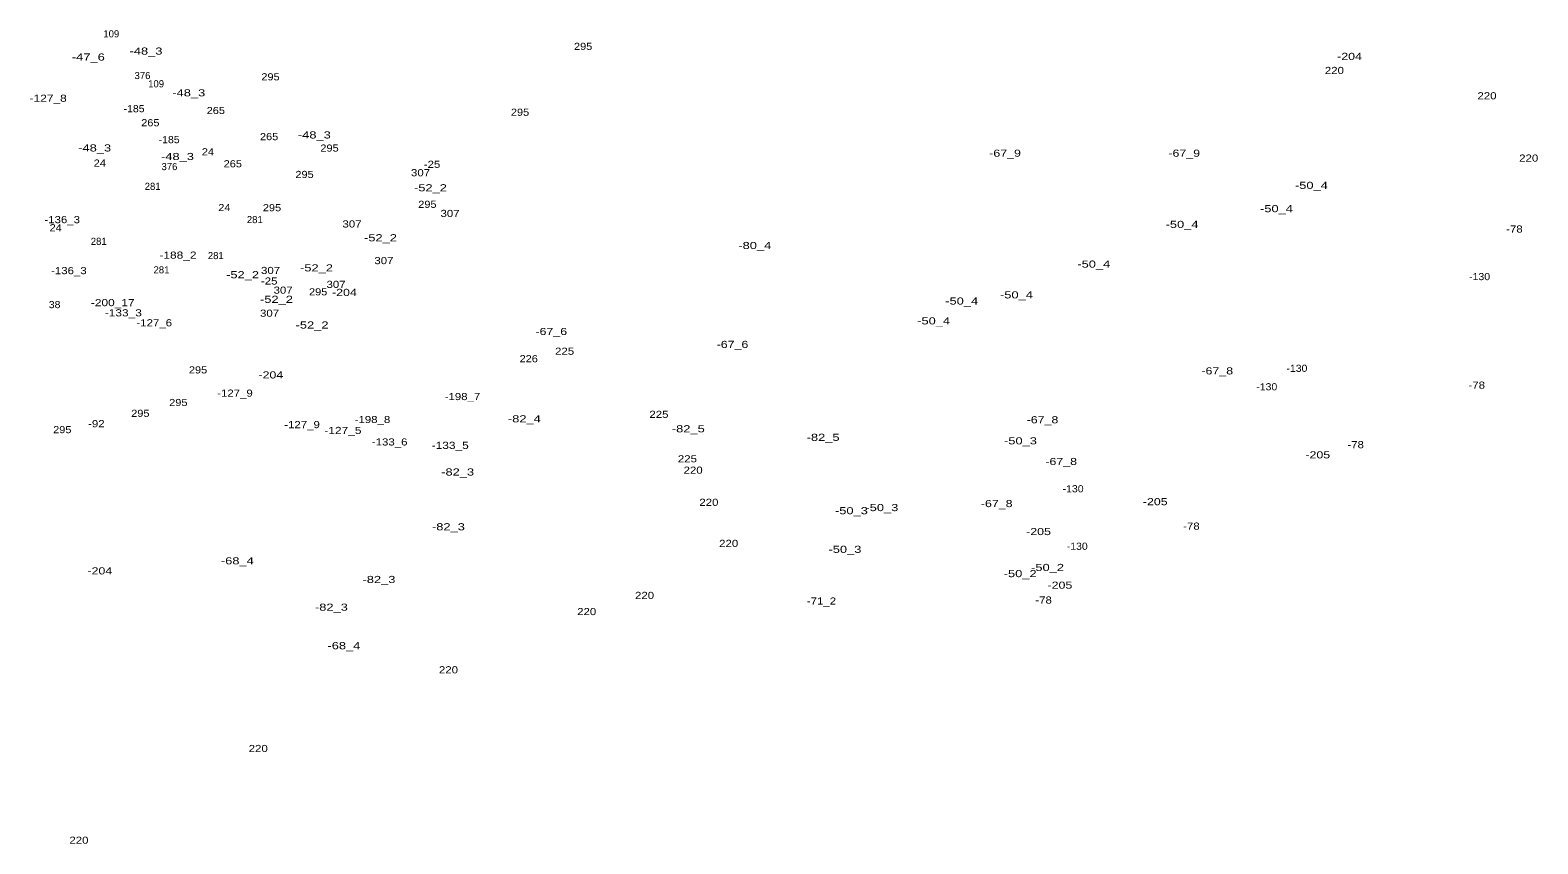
# Model space of a CAD drawing. Extents: x -662996 to -659766, y -998554 to -993949.
# Drawn here: x -660995 to -660149, y -995562 to -995106 of the extents above; entities that cross this region are included whole.
import ezdxf
from ezdxf.enums import TextEntityAlignment as Align

# ---------------------------------------------------------------- set-up
doc = ezdxf.new("R2010")
doc.units = 0
doc.header["$LTSCALE"] = 1.6
doc.layers.add('24', color=7, linetype='Continuous')

msp = doc.modelspace()

# ---------------------------------------------------------------- texts
at = {"layer": '24'}
for s, p in [('109', (-660949.441, -995109.63)), ('376', (-660931.938, -995133.05)), ('109', (-660924.291, -995137.67)), ('376', (-660916.798, -995184.14)), ('281', (-660926.22, -995195.24)), ('281', (-660868.9, -995213.9)), ('281', (-660956.49, -995226.1)), ('281', (-660921.27, -995242.1)), ('281', (-660890.799, -995234.1))]:
    msp.add_text(s, height=4, dxfattribs=at).set_placement(p, align=Align.CENTER)
for s, width, p in [('-47_6', 1.35, (-660962.311, -995122.64)), ('-48_3', 1.35, (-660929.95, -995119.32)), ('295', 1.15, (-660684.65, -995116.68)), ('-204', 1.3, (-660254.58, -995122.3)), ('220', 1.2, (-660263.079, -995130.19)), ('295', 1.15, (-660860.09, -995133.75)), ('-127_8', 1.25, (-660984.85, -995145.79)), ('-48_3', 1.35, (-660905.95, -995142.75)), ('220', 1.2, (-660177.449, -995144.41)), ('-185', 1.1, (-660936.65, -995151.64)), ('265', 1.15, (-660890.77, -995152.67)), ('295', 1.15, (-660720.07, -995153.63)), ('265', 1.15, (-660927.52, -995159.52)), ('-48_3', 1.35, (-660958.76, -995173.68)), ('-185', 1.1, (-660916.971, -995169.01)), ('265', 1.15, (-660860.87, -995167.33)), ('-48_3', 1.35, (-660835.49, -995166.38)), ('295', 1.15, (-660826.96, -995173.75)), ('24', 1.15, (-660955.87, -995182.17)), ('-48_3', 1.35, (-660912.29, -995178.48)), ('24', 1.15, (-660895.199, -995175.83)), ('265', 1.15, (-660881.25, -995182.57)), ('-25', 1.2, (-660769.44, -995182.88)), ('-67_9', 1.3, (-660447.89, -995176.63)), ('-67_9', 1.3, (-660347.35, -995176.63)), ('220', 1.2, (-660154.02, -995179.37)), ('295', 1.15, (-660840.98, -995188.55)), ('307', 1.2, (-660775.9, -995187.59)), ('-52_2', 1.35, (-660770.34, -995196.04)), ('-50_4', 1.35, (-660275.99, -995194.69)), ('24', 1.15, (-660885.98, -995207.14)), ('295', 1.15, (-660859.25, -995207.21)), ('295', 1.15, (-660772.05, -995205.31)), ('-50_4', 1.35, (-660295.58, -995207.75)), ('-136_3', 1.2, (-660976.981, -995213.92)), ('307', 1.2, (-660814.36, -995216.35)), ('307', 1.2, (-660759.33, -995210.44)), ('-50_4', 1.35, (-660348.57, -995216.59)), ('24', 1.15, (-660980.64, -995218.47)), ('-52_2', 1.35, (-660798.38, -995224.09)), ('-78', 1.2, (-660162.071, -995219.21)), ('-188_2', 1.25, (-660912.01, -995233.84)), ('-80_4', 1.35, (-660588.34, -995228.44)), ('-52_2', 1.35, (-660834.28, -995240.99)), ('307', 1.2, (-660796.46, -995236.92)), ('-50_4', 1.35, (-660398.11, -995238.87)), ('-136_3', 1.2, (-660973.24, -995242.54)), ('-52_2', 1.35, (-660875.76, -995244.83)), ('-25', 1.2, (-660860.83, -995248.38)), ('307', 1.2, (-660860.06, -995242.44)), ('307', 1.2, (-660823.31, -995250.25)), ('-130', 1.1, (-660181.601, -995245.89)), ('-52_2', 1.35, (-660856.75, -995258.66)), ('307', 1.2, (-660853.01, -995253.49)), ('295', 1.15, (-660833.36, -995254.45)), ('-204', 1.3, (-660818.61, -995254.76)), ('-50_4', 1.35, (-660441.5, -995256.15)), ('38', 1.1, (-660981.25, -995261.61)), ('-200_17', 1.25, (-660948.62, -995260.51)), ('-133_3', 1.25, (-660942.689, -995266.22)), ('307', 1.2, (-660860.63, -995266.44)), ('-50_4', 1.35, (-660472.22, -995259.61)), ('-127_6', 1.2, (-660925.32, -995271.81)), ('-52_2', 1.35, (-660836.78, -995273.07)), ('-50_4', 1.35, (-660487.97, -995270.75)), ('-67_6', 1.3, (-660702.53, -995276.71)), ('-67_6', 1.3, (-660600.85, -995283.95)), ('226', 1.15, (-660715.19, -995291.97)), ('225', 1.2, (-660695.059, -995287.78)), ('295', 1.15, (-660900.76, -995298.26)), ('-204', 1.3, (-660859.9, -995301.08)), ('-67_8', 1.3, (-660328.821, -995298.81)), ('-130', 1.1, (-660284.13, -995297.36)), ('-130', 1.1, (-660301.03, -995307.73)), ('-78', 1.2, (-660183.191, -995306.8)), ('295', 1.15, (-660911.81, -995316.55)), ('-127_9', 1.2, (-660880.03, -995311.3)), ('-198_7', 1.2, (-660752.36, -995313.22)), ('295', 1.15, (-660933.13, -995322.64)), ('-198_8', 1.2, (-660802.87, -995326.11)), ('-82_4', 1.35, (-660717.63, -995325.71)), ('225', 1.2, (-660642.13, -995323.21)), ('-67_8', 1.3, (-660426.88, -995326.24)), ('295', 1.15, (-660976.93, -995331.79)), ('-92', 1.2, (-660957.82, -995328.45)), ('-127_9', 1.2, (-660842.39, -995328.98)), ('-127_5', 1.25, (-660819.45, -995332.24)), ('-82_5', 1.35, (-660625.64, -995331.31)), ('-133_6', 1.2, (-660793.231, -995338.69)), ('-133_5', 1.25, (-660759.24, -995340.61)), ('-82_5', 1.35, (-660549.99, -995336.11)), ('-50_3', 1.35, (-660439.25, -995338.09)), ('-78', 1.2, (-660251.16, -995340.22)), ('225', 1.2, (-660626.13, -995348.17)), ('-67_8', 1.3, (-660416.4, -995349.67)), ('-205', 1.3, (-660272.41, -995345.95)), ('-82_3', 1.35, (-660755.069, -995355.57)), ('220', 1.2, (-660622.939, -995354.54)), ('-130', 1.1, (-660409.701, -995364.97)), ('220', 1.2, (-660614.1, -995372.59)), ('-50_3', 1.35, (-660534.11, -995377.27)), ('-50_3', 1.35, (-660517.02, -995375.54)), ('-67_8', 1.3, (-660452.581, -995373.29)), ('-205', 1.3, (-660363.61, -995372.23)), ('-78', 1.2, (-660343.321, -995385.94)), ('-82_3', 1.35, (-660760.25, -995386.31)), ('-205', 1.3, (-660429.11, -995388.99)), ('220', 1.2, (-660602.97, -995395.64)), ('-50_3', 1.35, (-660537.75, -995398.97)), ('-130', 1.1, (-660407.4, -995397.24)), ('-204', 1.3, (-660955.86, -995411.06)), ('-68_4', 1.35, (-660878.7, -995405.43)), ('-50_2', 1.35, (-660424.049, -995409.14)), ('-82_3', 1.35, (-660799.23, -995415.89)), ('-50_2', 1.35, (-660439.41, -995412.6)), ('-205', 1.3, (-660417.12, -995419.09)), ('220', 1.2, (-660650.199, -995424.84)), ('-71_2', 1.2, (-660550.94, -995428)), ('-78', 1.2, (-660426.27, -995427.43)), ('-82_3', 1.35, (-660825.919, -995431.44)), ('220', 1.2, (-660682.65, -995433.92)), ('-68_4', 1.35, (-660818.91, -995453.05)), ('220', 1.2, (-660760.22, -995466.58)), ('220', 1.2, (-660866.98, -995510.75)), ('220', 1.2, (-660967.59, -995562.23))]:
    msp.add_text(s, height=4, dxfattribs=dict(at, width=width)).set_placement(p, align=Align.CENTER)

doc.saveas('drawing.dxf')
